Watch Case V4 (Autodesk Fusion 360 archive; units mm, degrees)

design "Watch Case V4" references "6178 1.28in Round TFT (1)"
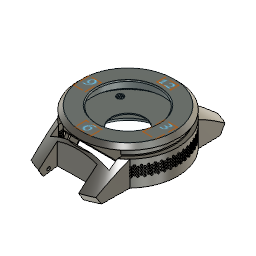
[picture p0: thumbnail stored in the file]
part number: 2025-11-16-21-07-14-550
description: Part Number
part number: 2025-12-12-19-54-11-448
part number: 2025-12-15-01-35-02-891
parameter "WatchHeight" = 11
parameter "ScreenHeight" = 5.4
parameter "OuterRingHeight" = 9
parameter "InnerRadius" = 22.5
parameter "CaseWidth" = 2
parameter "ScreenHolderWidth" = 1
parameter "HolderLength" = 8.5
parameter "WristBandWidth" = 20.5
parameter "BandHolderWidth" = 8.3
parameter "BandHolderAngle" = 7
parameter "ScreenDiameter" = 32.4
parameter "ScreenPanelWidth" = 13.21
parameter "ScreenPanelLength" = 29
parameter "BatteryWidth" = 30
parameter "BatteryLength" = 32
parameter "BatteryHeight" = 3.8
parameter "CaseThinWidth" = 0.5
parameter "PCBCaseHeight" = 8.8
parameter "CasePCBInner" = 15
parameter "InterLayerThick" = 0.5
parameter "kerf" = 0.2
parameter "BezelUnder" = 3
parameter "BezelThick" = 0.5
parameter "ScreenRealHeight" = 1.5
parameter "HapticDiameter" = 8
parameter "MtHoleDiameter" = 2.2
parameter "HapticHeight" = 2.7
parameter "HoneyCombDiameter" = 1
parameter "BandPinDiameter" = 1.75
parameter "CaseUpperHeight" = 3.6
parameter "ScreenOutletHeight" = 0.5
parameter "USBCLength" = 11.6
parameter "USBCWidth" = 6.7
parameter "IntToScreenHeight" = 4
parameter "ScreenFPCHeight" = 1.85
sketch "Sketch1" plane through (0, 0, 0) normal (1, 0, 0) x axis (0, 1, 0)
  line L1 (5889.1098, 2.4) -> (5889.1107, 8)
  line L2 (0, 9.1012) -> (0, -3.7988)
  line L3 (25.5, 20) -> (25.5, 0)
  line L4 (17, 5) -> (2, 5)
  line L5 (17, 5.5) -> (17, 5)
  line L6 (1.9251, 5.5) -> (17, 5.5)
  line L7 (25.5, 18.1465) -> (25.5, 18.6465)
  line L8 (2.0296, 13) -> (0.0012, 13.0012)
  line L9 (2.0275, 9.6) -> (2.0296, 13)
  line L10 (2, 15) -> (0.0012, 13.0012)
  line L11 (25.5, 15) -> (2, 15)
  line L12 (4, 9.6) -> (2.0275, 9.6)
  line L13 (25.5, 9.6) -> (4, 9.6)
  line L14 (25.5, 9.6) -> (25.5, 15)
  line L15 (7, -4.7988) -> (7, -3.7988)
  line L16 (2.5, -4.7988) -> (7, -4.7988)
  line L17 (0, -3.8) -> (2.5, -4.7988)
  line L18 (1.9251, 9.1) -> (1.9251, 5.5)
  line L19 (1.9251, 9.1) -> (0, 9.1012)
  line L20 (2, -3.7988) -> (0, -3.7988)
  line L21 (2, 5) -> (2, -3.7988)
  line L22 (3.5, -3.7988) -> (7, -3.7988)
  line L23 (3.5, -1.7988) -> (3.5, -3.7988)
  line L24 (2, -1.7988) -> (3.5, -1.7988)
  line L25 (0, -3.8) -> (2, -3.7988)
  point P13 (25.5, 18.6465)
  point P19 (25.5, 15)
  point P21 (25.5, 9.6)
  point P29 (2, -1.7988)
  point P2 (5889.1107, 8)
  point P3 (5889.1098, 2.4)
  point P4 (0, -3.7988)
  point P5 (0, 9.1012)
  point P9 (2, 5)
  point P10 (17, 5)
  point P11 (17, 5.5)
  point P14 (25.5, 18.1465)
  point P16 (2.0296, 13)
  point P17 (2.0275, 9.6)
  point P22 (7, -3.7988)
  point P23 (7, -4.7988)
  point P12 (1.9251, 5.5)
  point P25 (1.9251, 9.1)
  point P27 (3.5, -3.7988)
  point P28 (3.5, -1.7988)
  vertical L2
  vertical L3
  perpendicular L4 L5
  coincident L3 P13
  coincident L3 P19
  perpendicular L3 L11
  coincident L3 P21
  perpendicular L3 L13
  horizontal L6
  perpendicular L15 L16
  perpendicular L6 L18
  perpendicular L2 L20
  perpendicular L15 L22
  perpendicular L22 L23
  coincident L21 P29
  perpendicular L21 L24
  dimension "d4" distance P2 P3 = 5.6 (= "WatchHeight - ScreenHeight")
  dimension "d7" distance P4 P5 = 12.9 (= "PCBCaseHeight + InterLayerThick + CaseUpperHeight")
  dimension "d63" distance P9 P10 = 15 (= "CasePCBInner")
  dimension "d65" distance P10 P11 = 0.5 (= "InterLayerThick")
  dimension "d207" distance P13 P14 = 0.5
  dimension "d208" distance P16 P17 = 3.4
  dimension "d213" distance P19 P21 = 5.4
  dimension "d266" distance P4 P22 = 7
  dimension "d267" distance P22 P23 = 1
  dimension "d345" distance P12 P25 = 3.6
  dimension "d353" distance P27 P28 = 2
revolve "Revolve1" sketch "Sketch1" AlongAngle 360 bodies "Main Case"
sketch "Sketch2" plane through (0, 0, 0) normal (1, 0, 0) x axis (0, 1, 0)
  line L1 (-11.5686, -1.133) -> (0, 9.0996)
  line L2 (-9.3023, -5.1696) -> (-11.5686, -1.133)
  line L3 (0, -3.8) -> (-9.3023, -5.1696)
  line L4 (-10, 0) -> (0, 0)
  line L5 (0, 0) -> (-10, 0)
  line L6 (0, 13.2814) -> (0, -3.8)
  line L7 (0, -3.8) -> (0, 9.0996)
  point P2 (0, 9.0996)
  point P5 (0, -3.8)
  horizontal L4
  coincident P2 L6
  coincident P5 L6
work_axis "WorkAxis1"
revolve "Revolve2" sketch "Sketch2" AlongAngle 360
sketch "Sketch3" plane through (0, 0, 0) normal (0, 0, 1) x axis (1, 0, 0)
  line L1 (-10.25, 4.0598) -> (-10.25, 77.2482)
  line L2 (10.25, 77.2482) -> (10.25, 4.0598)
  line L3 (-14.6895, 74.4383) -> (-18.55, 42.9971)
  line L4 (14.6898, 74.436) -> (18.55, 42.9971)
  line L5 (-15.0653, -20.3776) -> (-18.55, 8.0029)
  line L6 (15.3944, -17.6975) -> (18.55, 8.0029)
  line L7 (-45.8114, 71.4038) -> (-14.6895, 74.4383)
  line L8 (-45.8114, -18.0283) -> (-45.8114, 71.4038)
  line L9 (-15.0653, -20.3776) -> (-45.8114, -18.0283)
  line L10 (45.0001, -17.6975) -> (15.3944, -17.6975)
  line L11 (45.0001, 74.3523) -> (45.0001, -17.6975)
  line L12 (14.6898, 74.436) -> (45.0001, 74.3523)
  line L13 (10.25, 77.2482) -> (-10.25, 77.2482)
  line L14 (10.25, 4.0598) -> (-10.25, 4.0598)
  line L15 (10.25, -18) -> (-10.25, -18)
  line L16 (10.25, -0.5377) -> (10.25, -18)
  line L17 (-10.25, -0.5377) -> (10.25, -0.5377)
  line L18 (-10.25, -18) -> (-10.25, -0.5377)
  circle C1 centre (0, 25.5) radius 25.5
  point P7 (-18.55, 42.9971)
  point P9 (18.55, 42.9971)
  point P11 (-18.55, 8.0029)
  point P13 (18.55, 8.0029)
  point P6 (0, 25.5)
  vertical L1
  vertical L2
  coincident C1 P7
  coincident C1 P9
  coincident C1 P11
  coincident C1 P13
  vertical L8
  horizontal L10
  perpendicular L10 L11
  perpendicular L2 L13
  perpendicular L2 L14
  horizontal L15
  vertical L16
  horizontal L17
  vertical L18
  dimension "d23" distance L1 P6 = 10.25
  dimension "d25" distance L2 P6 = 10.25 (= "WristBandWidth / 2")
  dimension "d27" distance P6 P11 = 18.55 (= "BandHolderWidth + WristBandWidth / 2")
  dimension "d28" distance P6 P13 = 18.55 (= "BandHolderWidth + WristBandWidth / 2")
  dimension "d29" distance P6 P9 = 18.55 (= "BandHolderWidth + WristBandWidth / 2")
  dimension "d30" distance P6 P7 = 18.55 (= "BandHolderWidth + WristBandWidth / 2")
  dimension "d32" angle L1 L3 = 7 (= "BandHolderAngle")
  dimension "d33" angle L2 L4 = 7 (= "BandHolderAngle")
  dimension "d34" angle L2 L6 = 7 (= "BandHolderAngle")
  dimension "d35" angle L1 L5 = 7 (= "BandHolderAngle")
  dimension "d219" distance P6 L16 = 10.25 (= "WristBandWidth / 2")
  dimension "d220" distance P6 L18 = 10.25 (= "WristBandWidth / 2")
extrude "Extrude1" cut sketch "Sketch3" profile of L1 L2 C1 L3 L4 L5 L6 L7 L8 L9 L10 L11 L12 L13 L15 L16 L17 L18 distance -15
sketch "Screen" plane through (0, 0, 0) normal (0, 0, 1) x axis (1, 0, 0)
  line L1 (33, 16.2) -> (-27, 16.2)
  line L2 (14.5, -12.8) -> (-14.5, -12.8)
  line L3 (14.5, -26.01) -> (14.5, -12.8)
  line L4 (-14.5, -26.01) -> (14.5, -26.01)
  line L5 (-14.5, -12.8) -> (-14.5, -26.01)
  line L6 (0, -26.01) -> (0, 16.2)
  circle C1 centre (0, 0) radius 16.2
  point P1 (0, 0)
  point P2 (0, 0)
  point P9 (0, 16.2)
  point P10 (0, -26.01)
  point P5 (-14.5, -12.8)
  point P6 (14.5, -12.8)
  point P8 (-14.5, -26.01)
  coincident P1 P2
  horizontal L1
  tangent C1 L1
  horizontal L2
  vertical L3
  horizontal L4
  vertical L5
  coincident C1 P9
  coincident L1 P9
  coincident L4 P10
  perpendicular L4 L6
  dimension "d41" diameter C1 = 32.4 (= "ScreenDiameter")
  dimension "d44" distance P5 P6 = 29 (= "ScreenPanelLength")
  dimension "d45" distance P5 P8 = 13.21 (= "ScreenPanelWidth")
  dimension "d46" distance L1 L2 = 29 (= "ScreenPanelLength")
  dimension "d47" distance L3 L6 = 14.5 (= "0.5 * ScreenPanelLength")
extrude "Extrude2" new body sketch "Screen" profile of C1 L2 L3 L4 L5 along normal blind 5.4 (= "ScreenHeight") bodies "Screen"
move "Move1"
move "Move2"
move "Move3"
sketch "Sketch7" plane through (0, 0, 0) normal (0, 0, 1) x axis (1, 0, 0)
sketch "Sketch8" plane through (0, 0, 0) normal (0, 0, 1) x axis (1, 0, 0)
sketch "Sketch9" plane through (0, 0, 0) normal (0, 0, 1) x axis (1, 0, 0)
  line L1 (32, 0) -> (0, 0)
  line L2 (32, 30) -> (32, 0)
  line L3 (0, 30) -> (32, 30)
  line L4 (0, 0) -> (0, 30)
  point P1 (0, 0)
  point P2 (0, 0)
  point P3 (32, 0)
  point P5 (0, 30)
  horizontal L1
  vertical L2
  horizontal L3
  vertical L4
  coincident P1 P2
  dimension "d53" distance P2 P3 = 32 (= "BatteryLength")
  dimension "d54" distance P2 P5 = 30 (= "BatteryWidth")
extrude "Extrude3" new body sketch "Sketch9" along normal blind 3.8 (= "BatteryHeight") bodies "Battery"
move "Move4"
sketch "Sketch10" plane through (0, 0, 0) normal (1, 0, 0) x axis (0, 1, 0)
sketch "USBC Port" plane through (0, 0, 0) normal (0, 1, 0) x axis (1, 0, 0)
  line L1 (11.6, 0) -> (0, 0)
  line L2 (11.6, -6.7) -> (11.6, 0)
  line L3 (0, -6.7) -> (11.6, -6.7)
  line L4 (0, 0) -> (0, -6.7)
  point P1 (0, 0)
  point P2 (0, 0)
  point P3 (11.6, 0)
  point P5 (0, -6.7)
  horizontal L1
  vertical L2
  horizontal L3
  vertical L4
  coincident P1 P2
  dimension "d370" distance P2 P3 = 11.6 (= "USBCLength")
  dimension "d371" distance P2 P5 = 6.7 (= "USBCWidth")
revolve "Revolve4" sketch "Sketch1" AlongAngle 360 bodies "Bezel"
component_insert "Component Insert"
sketch "Sketch41" plane through (0, 0, 15) normal (0, 0, 1) x axis (-1, 0, 0)
  circle C1 centre (0, -25.5) radius 23.5
  circle C2 centre (0, -25.5) radius 16.2
  concentric C1 C2
  dimension "d233" diameter C2 = 32.4 (= "ScreenDiameter")
extrude "Extrude22" cut sketch "Sketch41" profile of C2 against normal blind 0.5
fillet "Fillet3" radius 0.5
position "Position4"
sketch "Sketch43" plane through (0, 0, 9.6) normal (0, 0, -1) x axis (1, 0, 0)
  line L1 (-14.6107, -1.1137) -> (14.642, -1.1137)
  line L2 (-14.6107, -15.1775) -> (-14.6107, -1.1137)
  line L3 (14.642, -15.1775) -> (-14.6107, -15.1775)
  line L4 (14.642, -1.1137) -> (14.642, -15.1775)
  circle C1 centre (0, -25.5) radius 23.4725
  circle C2 centre (0, -25.5) radius 18.25
  concentric C1 C2
  horizontal L1
  vertical L2
  horizontal L3
  vertical L4
  dimension "d242" diameter C2 = 36.5
extrude "Extrude23" cut sketch "Sketch43" against normal blind 3.4
sketch "Sketch44" plane through (0, 0, 13) normal (0, 0, -1) x axis (1, 0, 0)
  arc A1 centre (0, -25.5) radius 23.4704 clockwise from (14.642, -7.1569) to (-14.6107, -7.1319)
  circle C1 centre (0, -25.5) radius 25.4988
  circle C2 centre (0, -25.5) radius 18.25
  arc A2 centre (0, -25.5) radius 23.4704 clockwise from (-14.6107, -7.1319) to (14.642, -7.1569)
  concentric A1 C2
extrude "Extrude24" cut sketch "Sketch44" profile of C2 against normal blind 1.5
base_feature "Base Feature1"
position "Position5"
position "Position6"
sketch "Sketch47" plane through (0, 0, 5.5) normal (0, 0, 1) x axis (-1, 0, 0)
  line L1 (0, -13) -> (10, -13)
  line L2 (0, -6) -> (0, -13)
  line L3 (10, -6) -> (0, -6)
  line L4 (10, -13) -> (10, -6)
  line L5 (-20.3751, -18.3494) -> (-22.3301, -18.3494)
  line L6 (-20.3751, -29.7219) -> (-20.3751, -18.3494)
  line L7 (-22.3301, -29.7219) -> (-20.3751, -29.7219)
  line L8 (-22.3301, -18.3494) -> (-22.3301, -29.7219)
  circle C1 centre (0, -25.5) radius 8.5
  circle C2 centre (0, -25.5) radius 23.5749
  horizontal L1
  vertical L2
  horizontal L3
  vertical L4
  horizontal L5
  vertical L6
  horizontal L7
  vertical L8
position "Position7"
work_plane "WorkPlane8" RotateAngle 0
sketch "Sketch50" plane through (-25.5, 0, 0) normal (-1, 0, 0) x axis (0, -1, 0)
  line L1 (-21.0533, 5.3267) -> (-34.6533, 5.3267)
  line L2 (-21.0533, -2.8733) -> (-21.0533, 5.3267)
  line L3 (-34.6533, -2.8733) -> (-21.0533, -2.8733)
  line L4 (-34.6533, 5.3267) -> (-34.6533, -2.8733)
  point P2 (-34.6533, 5.3267)
  point P5 (-34.6533, -2.8733)
  point P3 (-21.0533, 5.3267)
  horizontal L1
  vertical L2
  horizontal L3
  vertical L4
  dimension "d274" distance P2 P5 = 8.2 (= "USBCWidth + 1.5 mm")
  dimension "d275" distance P2 P3 = 13.6 (= "USBCLength + 2 mm")
sketch "Sketch51" plane through (-25.5, 0, 0) normal (-1, 0, 0) x axis (0, -1, 0)
  line L1 (-0.5215, -1.0155) -> (-0.8102, -1.5155)
  line L2 (-0.8102, -0.5155) -> (-0.5215, -1.0155)
  line L3 (-1.3876, -0.5155) -> (-0.8102, -0.5155)
  line L4 (-1.6762, -1.0155) -> (-1.3876, -0.5155)
  line L5 (-1.3876, -1.5155) -> (-1.6762, -1.0155)
  line L6 (-0.8102, -1.5155) -> (-1.3876, -1.5155)
  line L7 (-2.9758, -1.7646) -> (-2.6866, -1.2649)
  line L8 (-2.6876, -2.2649) -> (-2.9758, -1.7646)
  line L9 (-2.1103, -2.2655) -> (-2.6876, -2.2649)
  line L10 (-1.8211, -1.7658) -> (-2.1103, -2.2655)
  line L11 (-2.1093, -1.2655) -> (-1.8211, -1.7658)
  line L12 (-2.6866, -1.2649) -> (-2.1093, -1.2655)
  line L13 (-2.1093, -1.2655) -> (-1.6762, -1.0155)
  line L14 (-4.7103, -2.2655) -> (-5.2876, -2.2649)
  line L15 (-4.2762, -1.0155) -> (-3.9876, -0.5155)
  line L16 (-4.7093, -1.2655) -> (-4.2762, -1.0155)
  line L17 (-5.2876, -2.2649) -> (-5.5758, -1.7646)
  line L18 (-3.1215, -1.0155) -> (-3.4102, -1.5155)
  line L19 (-4.7093, -1.2655) -> (-4.4211, -1.7658)
  line L20 (-5.2866, -1.2649) -> (-4.7093, -1.2655)
  line L21 (-3.9876, -0.5155) -> (-3.4102, -0.5155)
  line L22 (-5.5758, -1.7646) -> (-5.2866, -1.2649)
  line L23 (-4.4211, -1.7658) -> (-4.7103, -2.2655)
  line L24 (-3.4102, -1.5155) -> (-3.9876, -1.5155)
  line L25 (-3.4102, -0.5155) -> (-3.1215, -1.0155)
  line L26 (-3.9876, -1.5155) -> (-4.2762, -1.0155)
  line L27 (-7.3103, -2.2655) -> (-7.8876, -2.2649)
  line L28 (-6.8762, -1.0155) -> (-6.5876, -0.5155)
  line L29 (-7.3093, -1.2655) -> (-6.8762, -1.0155)
  line L30 (-7.8876, -2.2649) -> (-8.1758, -1.7646)
  line L31 (-5.7215, -1.0155) -> (-6.0102, -1.5155)
  line L32 (-7.3093, -1.2655) -> (-7.0211, -1.7658)
  line L33 (-7.8866, -1.2649) -> (-7.3093, -1.2655)
  line L34 (-6.5876, -0.5155) -> (-6.0102, -0.5155)
  line L35 (-8.1758, -1.7646) -> (-7.8866, -1.2649)
  line L36 (-7.0211, -1.7658) -> (-7.3103, -2.2655)
  line L37 (-6.0102, -1.5155) -> (-6.5876, -1.5155)
  line L38 (-6.0102, -0.5155) -> (-5.7215, -1.0155)
  line L39 (-6.5876, -1.5155) -> (-6.8762, -1.0155)
  line L40 (-9.9103, -2.2655) -> (-10.4876, -2.2649)
  line L41 (-9.4762, -1.0155) -> (-9.1876, -0.5155)
  line L42 (-9.9093, -1.2655) -> (-9.4762, -1.0155)
  line L43 (-10.4876, -2.2649) -> (-10.7758, -1.7646)
  line L44 (-8.3215, -1.0155) -> (-8.6102, -1.5155)
  line L45 (-9.9093, -1.2655) -> (-9.6211, -1.7658)
  line L46 (-10.4866, -1.2649) -> (-9.9093, -1.2655)
  line L47 (-9.1876, -0.5155) -> (-8.6102, -0.5155)
  line L48 (-10.7758, -1.7646) -> (-10.4866, -1.2649)
  line L49 (-9.6211, -1.7658) -> (-9.9103, -2.2655)
  line L50 (-8.6102, -1.5155) -> (-9.1876, -1.5155)
  line L51 (-8.6102, -0.5155) -> (-8.3215, -1.0155)
  line L52 (-9.1876, -1.5155) -> (-9.4762, -1.0155)
  line L53 (-12.5103, -2.2655) -> (-13.0876, -2.2649)
  line L54 (-12.0762, -1.0155) -> (-11.7876, -0.5155)
  line L55 (-12.5093, -1.2655) -> (-12.0762, -1.0155)
  line L56 (-13.0876, -2.2649) -> (-13.3758, -1.7646)
  line L57 (-10.9215, -1.0155) -> (-11.2102, -1.5155)
  line L58 (-12.5093, -1.2655) -> (-12.2211, -1.7658)
  line L59 (-13.0866, -1.2649) -> (-12.5093, -1.2655)
  line L60 (-11.7876, -0.5155) -> (-11.2102, -0.5155)
  line L61 (-13.3758, -1.7646) -> (-13.0866, -1.2649)
  line L62 (-12.2211, -1.7658) -> (-12.5103, -2.2655)
  line L63 (-11.2102, -1.5155) -> (-11.7876, -1.5155)
  line L64 (-11.2102, -0.5155) -> (-10.9215, -1.0155)
  line L65 (-11.7876, -1.5155) -> (-12.0762, -1.0155)
  line L66 (-15.1103, -2.2655) -> (-15.6876, -2.2649)
  line L67 (-14.6762, -1.0155) -> (-14.3876, -0.5155)
  line L68 (-15.1093, -1.2655) -> (-14.6762, -1.0155)
  line L69 (-15.6876, -2.2649) -> (-15.9758, -1.7646)
  line L70 (-13.5215, -1.0155) -> (-13.8102, -1.5155)
  line L71 (-15.1093, -1.2655) -> (-14.8211, -1.7658)
  line L72 (-15.6866, -1.2649) -> (-15.1093, -1.2655)
  line L73 (-14.3876, -0.5155) -> (-13.8102, -0.5155)
  line L74 (-15.9758, -1.7646) -> (-15.6866, -1.2649)
  line L75 (-14.8211, -1.7658) -> (-15.1103, -2.2655)
  line L76 (-13.8102, -1.5155) -> (-14.3876, -1.5155)
  line L77 (-13.8102, -0.5155) -> (-13.5215, -1.0155)
  line L78 (-14.3876, -1.5155) -> (-14.6762, -1.0155)
  line L79 (-17.7103, -2.2655) -> (-18.2876, -2.2649)
  line L80 (-17.2762, -1.0155) -> (-16.9876, -0.5155)
  line L81 (-17.7093, -1.2655) -> (-17.2762, -1.0155)
  line L82 (-18.2876, -2.2649) -> (-18.5758, -1.7646)
  line L83 (-16.1215, -1.0155) -> (-16.4102, -1.5155)
  line L84 (-17.7093, -1.2655) -> (-17.4211, -1.7658)
  line L85 (-18.2866, -1.2649) -> (-17.7093, -1.2655)
  line L86 (-16.9876, -0.5155) -> (-16.4102, -0.5155)
  line L87 (-18.5758, -1.7646) -> (-18.2866, -1.2649)
  line L88 (-17.4211, -1.7658) -> (-17.7103, -2.2655)
  line L89 (-16.4102, -1.5155) -> (-16.9876, -1.5155)
  line L90 (-16.4102, -0.5155) -> (-16.1215, -1.0155)
  line L91 (-16.9876, -1.5155) -> (-17.2762, -1.0155)
  line L92 (-20.3103, -2.2655) -> (-20.8876, -2.2649)
  line L93 (-19.8762, -1.0155) -> (-19.5876, -0.5155)
  line L94 (-20.3093, -1.2655) -> (-19.8762, -1.0155)
  line L95 (-20.8876, -2.2649) -> (-21.1758, -1.7646)
  line L96 (-18.7215, -1.0155) -> (-19.0102, -1.5155)
  line L97 (-20.3093, -1.2655) -> (-20.0211, -1.7658)
  line L98 (-20.8866, -1.2649) -> (-20.3093, -1.2655)
  line L99 (-19.5876, -0.5155) -> (-19.0102, -0.5155)
  line L100 (-21.1758, -1.7646) -> (-20.8866, -1.2649)
  line L101 (-20.0211, -1.7658) -> (-20.3103, -2.2655)
  line L102 (-19.0102, -1.5155) -> (-19.5876, -1.5155)
  line L103 (-19.0102, -0.5155) -> (-18.7215, -1.0155)
  line L104 (-19.5876, -1.5155) -> (-19.8762, -1.0155)
  line L105 (-22.9103, -2.2655) -> (-23.4876, -2.2649)
  line L106 (-22.4762, -1.0155) -> (-22.1876, -0.5155)
  line L107 (-22.9093, -1.2655) -> (-22.4762, -1.0155)
  line L108 (-23.4876, -2.2649) -> (-23.7758, -1.7646)
  line L109 (-21.3215, -1.0155) -> (-21.6102, -1.5155)
  line L110 (-22.9093, -1.2655) -> (-22.6211, -1.7658)
  line L111 (-23.4866, -1.2649) -> (-22.9093, -1.2655)
  line L112 (-22.1876, -0.5155) -> (-21.6102, -0.5155)
  line L113 (-23.7758, -1.7646) -> (-23.4866, -1.2649)
  line L114 (-22.6211, -1.7658) -> (-22.9103, -2.2655)
  line L115 (-21.6102, -1.5155) -> (-22.1876, -1.5155)
  line L116 (-21.6102, -0.5155) -> (-21.3215, -1.0155)
  line L117 (-22.1876, -1.5155) -> (-22.4762, -1.0155)
  line L118 (-25.5103, -2.2655) -> (-26.0876, -2.2649)
  line L119 (-25.0762, -1.0155) -> (-24.7876, -0.5155)
  line L120 (-25.5093, -1.2655) -> (-25.0762, -1.0155)
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  point P6 (-1.6762, -1.0155)
  point P14 (-2.1093, -1.2655)
  horizontal L3
  perpendicular L5 L13
  dimension "d292" distance L3 L6 = 1
  dimension "d293" distance L9 L12 = 1
  dimension "d294" distance P6 P14 = 0.5
  dimension "d297" R-Pattern1-uDistance = -2.6
  dimension "d298" R-Pattern1-vDistance = -1.3
position "Position8"
combine "Combine1"
work_plane "WorkPlane9" RotateAngle 0
work_plane "WorkPlane10" RotateAngle 0
work_plane "WorkPlane11"
sketch "Sketch57" plane through (0, 0, 0) normal (-1, 0, 0) x axis (0, -1, 0)
  line L1 (0, -10) -> (0, 20)
  circle C1 centre (5, -3) radius 0.875
  circle C2 centre (-56, -3) radius 0.875
  point P2 (5, -3)
  point P3 (-56, -3)
  vertical L1
  dimension "d338" diameter C1 = 1.75 (= "BandPinDiameter")
  dimension "d339" diameter C2 = 1.75 (= "BandPinDiameter")
  dimension "d340" distance P2 L1 = 5
  dimension "d341" distance P2 P3 = 61 (= "51 mm + 5 * 2 mm")
extrude "Extrude36" cut sketch "Sketch57" profile of C1 distance 11.25 (= "( 22.5 / 2 ) * 1 mm")
work_plane "WorkPlane12" RotateAngle 0
sketch "Sketch58" plane through (-0.0055, 0, 9.0857) normal (0.0006, 0, -1) x axis (0, -1, 0)
  line L1 (-7.3775, 15.0728) -> (-1.9968, 0.0047)
  line L2 (-7.3645, -15.0681) -> (-1.9968, 0.0047)
  line L3 (-0.7645, -15.0681) -> (-7.3645, -15.0681)
  line L4 (-0.7775, 15.0728) -> (-7.3775, 15.0728)
  line L5 (-0.7645, -15.0681) -> (-0.7775, 15.0728)
  closed curve K1 centre (-25.5, -0.0055)
  point P3 (-7.3775, 15.0728)
  point P5 (-7.3645, -15.0681)
  point P2 (-1.9968, 0.0047)
  point P6 (-0.7645, -15.0681)
  point P7 (-0.7775, 15.0728)
  coincident P3 K1
  coincident K1 P5
  horizontal L3
  horizontal L4
  dimension "d347" distance P2 P3 = 16
  dimension "d348" distance P2 P5 = 16
  dimension "d349" distance P5 P6 = 6.6
  dimension "d350" distance P3 P7 = 6.6
extrude "Extrude37" new body sketch "Sketch58" along normal blind 12.9
revolve "Revolve6" sketch "Sketch1" AlongAngle 360 bodies "Base"
sketch "Sketch59" plane through (0, 0, -3.7988) normal (0, 0, -1) x axis (1, 0, 0)
  line L1 (15.0295, -7.4344) -> (-15.0295, -7.4344)
  line L2 (15.0295, -0.7344) -> (15.0295, -7.4344)
  line L3 (-15.0295, -0.7344) -> (15.0295, -0.7344)
  line L4 (-15.0295, -7.4344) -> (-15.0295, -0.7344)
  circle C1 centre (0, -25.5) radius 23.5
  arc A1 centre (0, -25.5) radius 25.5 clockwise from (-18.55, -8.0029) to (18.55, -8.0029)
  arc A2 centre (0, -25.5) radius 25.5 clockwise from (-18.55, -42.9971) to (-18.55, -8.0029)
  arc A3 centre (0, -25.5) radius 25.5 clockwise from (-10.25, -48.8493) to (-18.55, -42.9971)
  arc A4 centre (0, -25.5) radius 25.5 clockwise from (10.25, -48.8493) to (-10.25, -48.8493)
  arc A5 centre (0, -25.5) radius 25.5 clockwise from (18.55, -42.9971) to (10.25, -48.8493)
  arc A6 centre (0, -25.5) radius 25.5 clockwise from (18.55, -8.0029) to (18.55, -42.9971)
  point P9 (-15.0295, -7.4344)
  point P10 (15.0295, -7.4344)
  point P12 (-15.0295, -0.7344)
  horizontal L1
  vertical L2
  horizontal L3
  vertical L4
  coincident C1 P9
  coincident C1 P10
  dimension "d355" distance P9 P12 = 6.7
extrude "Extrude38" cut of existing geometry blind -15
extrude "Extrude39" cut sketch "Sketch59" profile of C1 L1 against normal blind 15 bodies "Main Case (1)"
sketch "Sketch61" plane through (0, 0, 0) normal (0, 0, 1) x axis (1, 0, 0)
  line L1 (-15.0211, 0.729) -> (15.0653, 0.729)
  line L2 (-15.0211, 7.4885) -> (-15.0211, 0.729)
  line L3 (15.0653, 7.4885) -> (-15.0211, 7.4885)
  line L4 (15.0653, 0.729) -> (15.0653, 7.4885)
  horizontal L1
  vertical L2
  horizontal L3
  vertical L4
sketch "Sketch62" plane through (0, 0, 0) normal (0, 0, 1) x axis (1, 0, 0)
extrude "Extrude40" new body sketch "Sketch59" profile of A1 L2 L3 L4 along normal blind 13
sketch "Sketch64" plane through (0, 0, -16.7988) normal (0, 0, -1) x axis (1, 0, 0)
  line L1 (15.0295, -0.7344) -> (15.0295, -4.8999)
  line L2 (6.0759, -0.7344) -> (15.0295, -0.7344)
  line L3 (-15.0535, -0.7344) -> (15.0295, -0.7344)
  line L4 (-15.0535, -7.4431) -> (-15.0535, -0.7344)
  line L5 (15.0295, -7.4431) -> (-15.0535, -7.4431)
  line L6 (15.0295, -0.7344) -> (15.0295, -7.4431)
  arc A1 centre (0, -25.5) radius 25.5 clockwise from (6.0759, -0.7344) to (15.0295, -4.8999)
  point P3 (15.0295, -0.7344)
  point P6 (15.0295, -0.7344)
  horizontal L3
  vertical L4
  horizontal L5
  vertical L6
  coincident P3 P6
extrude "Extrude41" cut sketch "Sketch64" against normal blind 15
sketch "Sketch65" plane through (0, 0, -1.7988) normal (0, 0, 1) x axis (-1, 0, 0)
  circle C1 centre (0, -25.5) radius 23.5
  circle C2 centre (0, -25.5) radius 22
base_feature "Base Feature1"
position "Position10"
sketch "Sketch66" plane through (-0.0055, 0, 9.0857) normal (0.0006, 0, -1) x axis (0, -1, 0)
  circle C1 centre (-35.4273, -14.2497) radius 1.75
  dimension "d365" diameter C1 = 3.5
sketch "Sketch67" plane through (0, 0, 5.5) normal (0, 0, 1) x axis (-1, 0, 0)
  line L1 (-15.0295, -7.4344) -> (15.0295, -7.4344)
  line L2 (-15.061, -7.3631) -> (-14.8531, -7.2891)
  line L3 (15.0761, -7.3775) -> (15.0761, -7.3757)
  line L4 (14.8722, -7.3047) -> (15.0761, -7.3775)
  arc A1 centre (0, -25.5) radius 23.5 clockwise from (14.8722, -7.3047) to (15.0295, -7.4344)
  arc A2 centre (0, -25.5) radius 23.5 clockwise from (-15.0295, -7.4344) to (-14.8531, -7.2891)
  arc A3 centre (0, -25.5) radius 23.5749 clockwise from (15.0761, -7.3757) to (-15.061, -7.3631)
  circle C1 centre (0, -25.5) radius 8.5
  circle C2 centre (15.4774, -36.9546) radius 1.75
  circle C3 centre (-14.2212, -35.4445) radius 1.75
  dimension "d366" diameter C2 = 3.5
  dimension "d367" diameter C3 = 3.5
extrude "Extrude42" cut sketch "Sketch67" profile of C2 C3 against normal blind 0.5
emboss "Emboss7" sketch "USBC Port" Depth -2 Horizontal Distance -6 Vertical Distance 2.5 Rotation Angle 0
emboss "Emboss8" sketch "Sketch51" Depth -2 Horizontal Distance 0 Vertical Distance 7 Rotation Angle 0
sketch "Sketch68" plane through (0, 0, 15) normal (0, 0, 1) x axis (-1, 0, 0)
  dimension "d380" = 5
  dimension "d381" = "12"
  dimension "d382" = 5
  dimension "d383" = 0 (= "Text2-Text")
  dimension "d384" = 5
  dimension "d385" = 0 (= "Text3-Text")
  dimension "d386" = 5
  dimension "d387" = 0 (= "Text4-Text")
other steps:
create_component "CreateComponent5"
create_component "CreateComponent8"
named bodies: "Main Case", "Screen", "Battery", "Bezel", "Base", "Main Case (1)"

design "6178 1.28in Round TFT (1)"
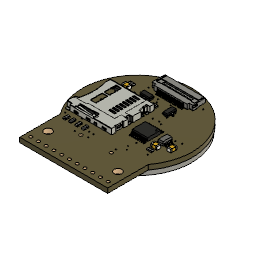
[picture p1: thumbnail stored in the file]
description: Part Number
part number: PCB Component
part number: 10uF
part number: 0.1uF
part number: APX803-SAG
part number: 74HC4050PWR
part number: DISP_LCD_GENERIC_SPI_1.28_240X240_ROUND
part number: AP2112K-3.3
part number: Board
part number: EYE_SPI_DISPLAY_FLIP
part number: MicroSD
base_feature "Base Feature1"
base_feature "Base Feature1"
base_feature "Base Feature1"
base_feature "Base Feature1"
base_feature "Base Feature1"
base_feature "Base Feature1"
base_feature "Base Feature1"
base_feature "Base Feature1"
base_feature "Base Feature1"
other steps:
create_component "CreateComponent1"
create_component "CreateComponent2"
create_component "CreateComponent3"
create_component "CreateComponent4"
create_component "CreateComponent5"
create_component "CreateComponent6"
create_component "CreateComponent7"
create_component "CreateComponent8"
create_component "CreateComponent9"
